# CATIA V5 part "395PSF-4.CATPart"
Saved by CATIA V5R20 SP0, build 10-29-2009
Part number: 395PSF-4
Source: Unknown
Property "ARTICLENO": "395PSF-4"
Property "BOMINFO": "395PSF-4"
Property "CODE": "395PSF-4"
Property "D": "53.000"
Property "D1": "65.000"
Property "H": "7.500"
Property "L": "282.000"
Property "L1": "10.000"
Property "L2": "235.000"
Property "L3": "16.000"
Property "L4": "10.000"
Property "LINA": "395PSF-4"
Property "MAXLOAD": "8000 Kg"
Property "MDW": "16000 Kg"
Property "NB": "395PSF-4"
Property "NBSYN": "$CODE."
Property "NN": "395PSF"
Property "NT": "FIAT Lifting Pins"
Property "SUPPLIER": "CF"
Bounding box of the stored display mesh (mm): x 0 to 282, y -34 to 32.5, z -32.5 to 32.5
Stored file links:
  C:\Users\Utente\Desktop\3D files 395PSF\395PSF-4.CATPart
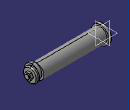
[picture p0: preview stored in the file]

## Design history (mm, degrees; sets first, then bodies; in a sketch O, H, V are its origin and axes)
Body1 "Geometry.1" (main body)
  Solid1 "395PSF-4.catpart": solid without history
